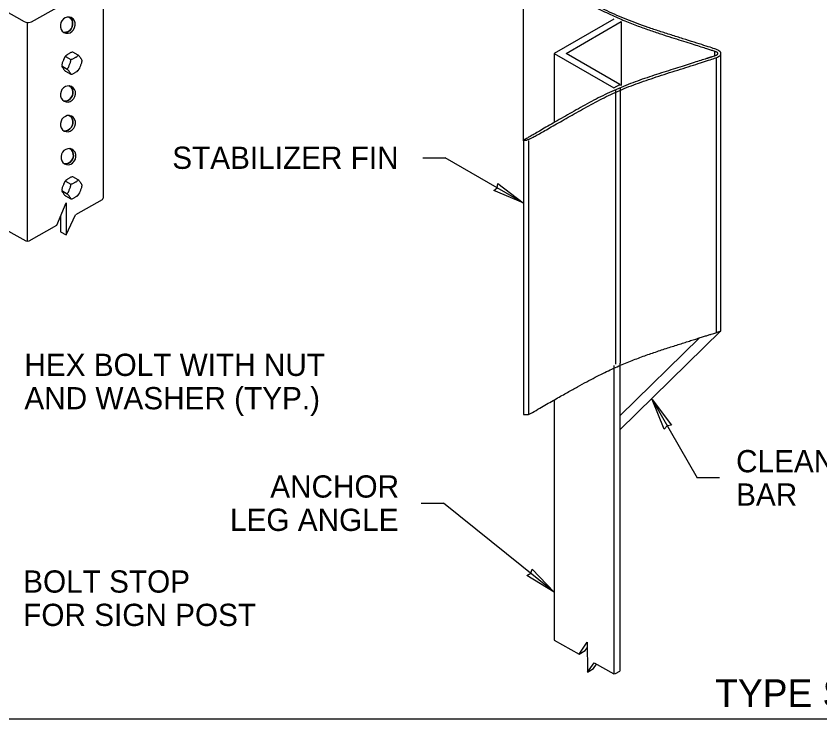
# Model space of a CAD drawing. Extents: x 99862 to 103680, y 99470 to 102076.
# Drawn here: x 101059 to 101638, y 100000 to 100505 of the extents above; entities that cross this region are included whole.
import ezdxf

# ---------------------------------------------------------------- set-up
doc = ezdxf.new("R2010")
doc.units = 0
for name, color, linetype in [('Level 1', 7, 'Continuous'), ('Level 11', 7, 'Continuous'), ('Level 13', 7, 'Continuous'), ('Level 15', 7, 'Continuous'), ('Level 2', 7, 'Continuous'), ('Level 20', 7, 'Continuous'), ('Level 27', 7, 'Continuous'), ('Level 3', 7, 'Continuous'), ('Level 4', 7, 'Continuous'), ('Level 6', 7, 'Continuous')]:
    doc.layers.add(name, color=color, linetype=linetype)

msp = doc.modelspace()

# ---------------------------------------------------------------- linework, layer by layer
at = {"layer": 'Level 1'}
msp.add_lwpolyline([(99862, 99999.5), (103151, 99999.5), (103151, 102075.5), (99862, 102075.5)], close=True, dxfattribs=at)
at = {"layer": 'Level 11'}
for p, q in [((101489.46, 100503.03), (101446.57, 100478.27)), ((101455.05, 100478.27), (101494.78, 100501.2)), ((101494.78, 100501.2), (101494.78, 100455.22)), ((101493.65, 100456.03), (101493.65, 100455.11))]:
    msp.add_line(p, q, dxfattribs=at)
msp.add_open_spline([(101566.46, 100478.33), (101566.46, 100478.39), (101566.45, 100478.45)], degree=2, dxfattribs=at)
at = {"layer": 'Level 13'}
for p, q in [((101094.75, 100476.2), (101098.62, 100473.97)), ((101103.97, 100477.06), (101100.11, 100479.29)), ((101092.08, 100469.3), (101095.94, 100467.07)), ((101094.75, 100465.5), (101098.62, 100463.27)), ((101103.97, 100387.36), (101100.11, 100389.59)), ((101094.75, 100386.5), (101098.62, 100384.27)), ((101092.08, 100379.61), (101095.94, 100377.38)), ((101094.75, 100375.8), (101098.62, 100373.57))]:
    msp.add_line(p, q, dxfattribs=at)
for points, degree in [([(101094.33, 100475.75), (101093.78, 100475), (101093.39, 100473.89), (101093.03, 100472.97), (101092.67, 100472.03), (101092.19, 100470.92), (101092.08, 100469.81), (101092.07, 100469.71), (101092.07, 100469.62)], 3), ([(101094.97, 100476.55), (101094.75, 100476.29), (101094.53, 100476.02), (101094.33, 100475.75)], 2), ([(101100.11, 100479.29), (101099.91, 100479.27), (101099.72, 100479.22), (101098.62, 100478.92), (101097.78, 100478.39), (101097.05, 100477.97), (101096.33, 100477.55), (101095.43, 100477.07), (101094.97, 100476.55)], 3), ([(101098.62, 100473.97), (101098.81, 100474), (101099.01, 100474.04), (101100.1, 100474.35), (101100.95, 100474.87), (101101.68, 100475.3), (101102.41, 100475.72), (101103.32, 100476.2), (101103.85, 100476.84), (101103.93, 100476.95), (101103.97, 100477.06)], 3), ([(101106.66, 100473.31), (101106.65, 100473.35), (101106.65, 100473.38), (101106.53, 100473.77), (101106.06, 100474.42), (101105.69, 100474.94), (101105.33, 100475.46), (101104.92, 100476.06), (101104.23, 100476.8), (101104.1, 100476.94), (101103.97, 100477.06)], 3), ([(101092.07, 100469.24), (101092.07, 100469.21), (101092.08, 100469.18), (101092.19, 100468.79), (101092.67, 100468.14), (101093.03, 100467.62), (101093.4, 100467.1), (101093.8, 100466.5), (101094.49, 100465.76), (101094.62, 100465.62), (101094.75, 100465.5)], 3), ([(101095.94, 100467.07), (101096.07, 100467.18), (101096.2, 100467.32), (101096.89, 100468.21), (101097.3, 100469.36), (101097.66, 100470.3), (101098.03, 100471.24), (101098.5, 100472.35), (101098.63, 100473.57), (101098.63, 100473.78), (101098.62, 100473.97)], 3), ([(101104.39, 100466.81), (101104.95, 100467.56), (101105.34, 100468.67), (101105.69, 100469.58), (101106.06, 100470.53), (101106.53, 100471.64), (101106.65, 100472.75), (101106.65, 100472.84), (101106.65, 100472.94)], 3), ([(101106.65, 100472.94), (101106.66, 100473.05), (101106.66, 100473.16), (101106.66, 100473.28), (101106.66, 100473.3), (101106.66, 100473.31)], 3), ([(101098.62, 100463.27), (101098.63, 100463.31), (101098.63, 100463.37), (101098.5, 100463.79), (101098.03, 100464.43), (101097.66, 100464.95), (101097.3, 100465.47), (101096.89, 100466.07), (101096.2, 100466.81), (101096.07, 100466.95), (101095.94, 100467.07)], 3), ([(101098.62, 100463.27), (101098.81, 100463.29), (101099.01, 100463.33), (101100.1, 100463.64), (101100.95, 100464.17), (101101.68, 100464.59), (101102.4, 100465.01), (101103.29, 100465.48), (101103.75, 100466.01)], 3), ([(101103.75, 100466.01), (101103.98, 100466.27), (101104.19, 100466.54), (101104.39, 100466.81)], 2), ([(101100.11, 100389.59), (101099.91, 100389.57), (101099.72, 100389.53), (101098.62, 100389.22), (101097.78, 100388.69), (101097.05, 100388.27), (101096.33, 100387.85), (101095.43, 100387.38), (101094.97, 100386.85)], 3), ([(101094.33, 100386.05), (101093.78, 100385.3), (101093.39, 100384.19), (101093.03, 100383.28), (101092.67, 100382.33), (101092.19, 100381.22), (101092.08, 100380.11), (101092.07, 100380.02), (101092.07, 100379.92)], 3), ([(101094.97, 100386.85), (101094.75, 100386.59), (101094.53, 100386.32), (101094.33, 100386.05)], 2), ([(101095.94, 100377.38), (101096.07, 100377.48), (101096.2, 100377.62), (101096.89, 100378.51), (101097.3, 100379.66), (101097.66, 100380.6), (101098.03, 100381.55), (101098.5, 100382.66), (101098.63, 100383.87), (101098.63, 100384.08), (101098.62, 100384.27)], 3), ([(101098.62, 100384.27), (101098.81, 100384.3), (101099.01, 100384.34), (101100.1, 100384.65), (101100.95, 100385.17), (101101.68, 100385.6), (101102.41, 100386.02), (101103.32, 100386.51), (101103.85, 100387.14), (101103.93, 100387.25), (101103.97, 100387.36)], 3), ([(101106.66, 100383.62), (101106.65, 100383.65), (101106.65, 100383.68), (101106.53, 100384.08), (101106.06, 100384.72), (101105.69, 100385.24), (101105.33, 100385.76), (101104.92, 100386.36), (101104.23, 100387.1), (101104.1, 100387.24), (101103.97, 100387.36)], 3), ([(101104.39, 100377.11), (101104.95, 100377.86), (101105.34, 100378.97), (101105.69, 100379.89), (101106.06, 100380.83), (101106.53, 100381.94), (101106.65, 100383.05), (101106.65, 100383.15), (101106.65, 100383.24)], 3), ([(101106.65, 100383.24), (101106.66, 100383.35), (101106.66, 100383.46), (101106.66, 100383.58), (101106.66, 100383.6), (101106.66, 100383.62)], 3), ([(101092.07, 100379.55), (101092.07, 100379.51), (101092.08, 100379.48), (101092.19, 100379.09), (101092.67, 100378.44), (101093.03, 100377.92), (101093.4, 100377.4), (101093.8, 100376.8), (101094.49, 100376.06), (101094.62, 100375.93), (101094.75, 100375.8)], 3), ([(101098.62, 100373.57), (101098.63, 100373.61), (101098.63, 100373.67), (101098.5, 100374.09), (101098.03, 100374.73), (101097.66, 100375.25), (101097.3, 100375.77), (101096.89, 100376.38), (101096.2, 100377.12), (101096.07, 100377.25), (101095.94, 100377.38)], 3), ([(101103.75, 100376.31), (101103.98, 100376.57), (101104.19, 100376.84), (101104.39, 100377.11)], 2), ([(101098.62, 100373.57), (101098.81, 100373.59), (101099.01, 100373.64), (101100.1, 100373.94), (101100.95, 100374.47), (101101.68, 100374.89), (101102.4, 100375.31), (101103.29, 100375.79), (101103.75, 100376.31)], 3)]:
    msp.add_open_spline(points, degree=degree, dxfattribs=at)
at = {"layer": 'Level 15'}
for p, q in [((101351.94, 100403.24), (101367.94, 100403.24)), ((101424.23, 100370.74), (101367.94, 100403.24)), ((101516.89, 100229.24), (101549.39, 100172.95)), ((101565.39, 100172.95), (101549.39, 100172.95)), ((101350.71, 100154.74), (101366.71, 100154.74)), ((101446.57, 100090.71), (101366.71, 100154.74))]:
    msp.add_line(p, q, dxfattribs=at)
for points in [[(101424.23, 100370.74), (101402.97, 100379.57), (101405.37, 100381.62), (101405.95, 100384.74)], [(101516.89, 100229.24), (101530.89, 100210.96), (101527.78, 100210.39), (101525.72, 100207.98)], [(101446.57, 100090.71), (101426.89, 100102.66), (101429.58, 100104.33), (101430.62, 100107.32)]]:
    msp.add_lwpolyline(points, close=True, dxfattribs=at)
at = {"layer": 'Level 2'}
msp.add_line((101067.52, 100343.25), (101067.52, 100500.5), dxfattribs=at)
for points in [[(101014.23, 100530.06), (101014.28, 100530.01), (101014.7, 100529.73), (101064.97, 100501.29), (101066.1, 100500.87), (101067.1, 100500.59), (101068.23, 100500.59), (101069.37, 100500.87), (101070.36, 100501.15), (101120.91, 100529.59), (101121.15, 100529.82)], [(101121.77, 100530.84), (101121.77, 100374.05), (101121.7, 100373.94)], [(101093.65, 100493.38), (101095.07, 100493.52), (101096.49, 100493.93), (101097.77, 100494.91), (101098.76, 100496.02), (101099.62, 100497.4), (101099.9, 100499.07), (101099.9, 100500.73), (101099.47, 100502.26), (101098.62, 100503.51), (101097.34, 100504.48), (101095.92, 100504.34), (101094.5, 100503.92), (101093.23, 100503.09), (101092.23, 100501.84), (101091.38, 100500.46), (101091.1, 100498.79), (101091.1, 100497.13), (101091.52, 100495.6), (101092.37, 100494.35), (101093.65, 100493.38)], [(101093.65, 100493.38), (101095.07, 100492.96), (101096.63, 100492.82), (101098.05, 100493.24), (101099.47, 100494.21), (101100.61, 100495.32), (101101.32, 100496.85), (101101.75, 100498.65), (101101.75, 100500.32), (101101.18, 100501.84), (101100.18, 100503.09), (101098.91, 100504.06), (101097.34, 100504.48), (101098.62, 100503.51), (101099.47, 100502.26), (101099.9, 100500.73), (101099.9, 100499.07), (101099.62, 100497.4), (101098.76, 100496.02), (101097.77, 100494.91), (101096.49, 100493.93), (101095.07, 100493.52), (101093.65, 100493.38)], [(101093.79, 100443.89), (101095.21, 100444.03), (101096.63, 100444.45), (101097.91, 100445.28), (101098.91, 100446.53), (101099.76, 100447.92), (101100.04, 100449.58), (101100.04, 100451.25), (101099.62, 100452.77), (101098.76, 100454.02), (101097.49, 100454.99), (101096.07, 100454.85), (101094.65, 100454.44), (101093.37, 100453.61), (101092.23, 100452.36), (101091.52, 100450.97), (101091.24, 100449.3), (101091.24, 100447.64), (101091.66, 100446.11), (101092.52, 100444.86), (101093.79, 100443.89)], [(101093.79, 100443.89), (101095.21, 100443.48), (101096.63, 100443.34), (101098.2, 100443.75), (101099.62, 100444.73), (101100.75, 100445.84), (101101.46, 100447.36), (101101.89, 100449.03), (101101.89, 100450.83), (101101.32, 100452.36), (101100.33, 100453.61), (101099.05, 100454.58), (101097.49, 100454.99), (101098.76, 100454.02), (101099.62, 100452.77), (101100.04, 100451.25), (101100.04, 100449.58), (101099.76, 100447.92), (101098.91, 100446.53), (101097.91, 100445.28), (101096.63, 100444.45), (101095.21, 100444.03), (101093.79, 100443.89)], [(101093.79, 100422.48), (101095.21, 100422.62), (101096.63, 100423.03), (101097.91, 100424), (101098.91, 100425.11), (101099.76, 100426.64), (101100.04, 100428.17), (101100.04, 100429.83), (101099.62, 100431.36), (101098.76, 100432.61), (101097.49, 100433.58), (101096.07, 100433.58), (101094.65, 100433.02), (101093.37, 100432.19), (101092.23, 100430.94), (101091.52, 100429.55), (101091.24, 100427.89), (101091.24, 100426.22), (101091.66, 100424.7), (101092.52, 100423.45), (101093.79, 100422.48)], [(101093.79, 100422.48), (101095.21, 100422.06), (101096.63, 100421.92), (101098.2, 100422.48), (101099.62, 100423.31), (101100.75, 100424.56), (101101.46, 100425.95), (101101.89, 100427.75), (101101.89, 100429.42), (101101.32, 100430.94), (101100.33, 100432.33), (101099.05, 100433.16), (101097.49, 100433.58), (101098.76, 100432.61), (101099.62, 100431.36), (101100.04, 100429.83), (101100.04, 100428.17), (101099.76, 100426.64), (101098.91, 100425.11), (101097.91, 100424), (101096.63, 100423.03), (101095.21, 100422.62), (101093.79, 100422.48)], [(101094.08, 100398.75), (101095.5, 100398.89), (101096.92, 100399.31), (101098.2, 100400.14), (101099.33, 100401.39), (101100.04, 100402.78), (101100.47, 100404.44), (101100.33, 100406.11), (101099.9, 100407.63), (101099.05, 100408.88), (101097.91, 100409.85), (101096.35, 100409.71), (101094.93, 100409.3), (101093.65, 100408.46), (101092.66, 100407.22), (101091.95, 100405.83), (101091.52, 100404.16), (101091.52, 100402.5), (101092.09, 100400.97), (101092.94, 100399.72), (101094.08, 100398.75)], [(101094.08, 100398.75), (101095.5, 100398.34), (101097.06, 100398.2), (101098.62, 100398.61), (101099.9, 100399.45), (101101.04, 100400.69), (101101.89, 100402.22), (101102.17, 100403.89), (101102.17, 100405.69), (101101.6, 100407.22), (101100.61, 100408.46), (101099.33, 100409.44), (101097.91, 100409.85), (101099.05, 100408.88), (101099.9, 100407.63), (101100.33, 100406.11), (101100.47, 100404.44), (101100.04, 100402.78), (101099.33, 100401.39), (101098.2, 100400.14), (101096.92, 100399.31), (101095.5, 100398.89), (101094.08, 100398.75)], [(101067.38, 100343.25), (101068.52, 100343.53), (101088.54, 100354.63), (101095.21, 100370.86), (101095.21, 100347.83), (101102.03, 100362.12)], [(101121.7, 100373.94), (101121.2, 100373.08), (101102.03, 100362.12)], [(101034.16, 100361.43), (101039.98, 100370.17), (101040.12, 100348.39), (101044.95, 100355.32), (101066.1, 100343.39), (101067.52, 100343.25)], [(101091.1, 100360.87), (101091.1, 100350.05), (101095.21, 100347.83)]]:
    msp.add_lwpolyline(points, dxfattribs=at)
at = {"layer": 'Level 27'}
for p, q in [((101563.33, 100277.53), (101563.33, 100475.2)), ((101490.91, 100254.7), (101490.91, 100452.17)), ((101494.15, 100255.42), (101494.15, 100453.1))]:
    msp.add_line(p, q, dxfattribs=at)
at = {"layer": 'Level 3'}
for p, q in [((101446.57, 100478.27), (101446.57, 100428.85)), ((101446.57, 100478.27), (101489.37, 100453.56)), ((101493.65, 100456.03), (101455.13, 100478.27)), ((101489.37, 100453.56), (101493.65, 100456.03)), ((101493.65, 100255.56), (101493.65, 100033.91)), ((101489.37, 100253.81), (101489.37, 100031.95)), ((101446.57, 100229.1), (101446.57, 100163.45)), ((101446.57, 100163.45), (101446.57, 100056.13))]:
    msp.add_line(p, q, dxfattribs=at)
for points in [[(101446.57, 100056.13), (101464.37, 100046.2)], [(101464.37, 100046.2), (101470.19, 100054.81), (101470.33, 100033.02), (101475.16, 100039.96), (101489.36, 100031.95)], [(101464.37, 100046.2), (101468.77, 100048.7), (101470.19, 100050.64)], [(101470.33, 100033.02), (101474.74, 100035.66), (101476.87, 100038.85)], [(101489.37, 100031.94), (101490.67, 100032.26), (101493.65, 100033.91)]]:
    msp.add_lwpolyline(points, dxfattribs=at)
at = {"layer": 'Level 4'}
for p, q in [((101424.44, 100415.97), (101424.44, 100540.53)), ((101562.13, 100476.45), (101562.13, 100479.97)), ((101566.48, 100278.65), (101566.48, 100478.27)), ((101424.44, 100415.53), (101424.44, 100415.97)), ((101424.45, 100415.49), (101424.45, 100218.41)), ((101428.05, 100415.49), (101428.05, 100218.44))]:
    msp.add_line(p, q, dxfattribs=at)
for points, degree in [([(101566.45, 100478.45), (101566.22, 100480.34), (101563.34, 100481.25), (101527.44, 100492.57), (101491.54, 100503.88), (101459.78, 100522.22), (101428.01, 100540.56), (101426.23, 100540.56), (101424.45, 100540.56), (101424.48, 100540.54), (101424.51, 100540.53)], 4), ([(101424.73, 100540.4), (101457.37, 100521.55), (101490.02, 100502.71), (101526.07, 100491.34), (101562.13, 100479.97), (101563.94, 100479.4), (101563.94, 100478.21), (101563.94, 100477.02), (101562.13, 100476.45), (101526.07, 100465.08), (101490.02, 100453.72), (101457.4, 100434.88), (101424.77, 100416.05), (101424.61, 100415.95), (101424.45, 100415.86), (101426.23, 100415.86), (101428.01, 100415.86), (101459.78, 100434.2), (101491.54, 100452.54), (101527.44, 100463.85), (101563.34, 100475.17), (101566.34, 100476.12), (101566.46, 100478.09)], 4), ([(101428.06, 100218.41), (101459.48, 100236.55), (101490.91, 100254.7), (101527.12, 100266.11), (101563.33, 100277.53), (101565.02, 100278.06), (101566.48, 100278.65)], 4), ([(101424.46, 100218.41), (101426.26, 100218.41), (101428.06, 100218.41)], 2)]:
    msp.add_open_spline(points, degree=degree, dxfattribs=at)
at = {"layer": 'Level 6'}
for p, q in [((101493.65, 100207.37), (101566.48, 100278.65)), ((101550.96, 100273.63), (101493.65, 100217.53))]:
    msp.add_line(p, q, dxfattribs=at)

# ---------------------------------------------------------------- texts
at = {"layer": 'Level 20'}
for s, height, p in [('STABILIZER FIN', 16, (101171.59, 100395.24)), ('ANCHOR', 16, (101242.12, 100158.74)), ('LEG ANGLE', 16, (101213.17, 100134.74)), ('TYPE ST-3', 20, (101562.36, 100007.98))]:
    msp.add_text(s, height=height, dxfattribs=at).set_placement(p)
for s, p in [('HEX BOLT WITH NUT ', (101065.17, 100246.26)), ('AND WASHER (TYP.)', (101065.17, 100222.26)), ('CLEAN OUT', (101577.39, 100176.95)), ('BAR', (101577.39, 100152.95)), ('BOLT STOP', (101064.31, 100090.36)), ('FOR SIGN POST', (101064.31, 100066.36))]:
    msp.add_text(s, height=16, rotation=360, dxfattribs=at).set_placement(p)

doc.saveas('drawing.dxf')
